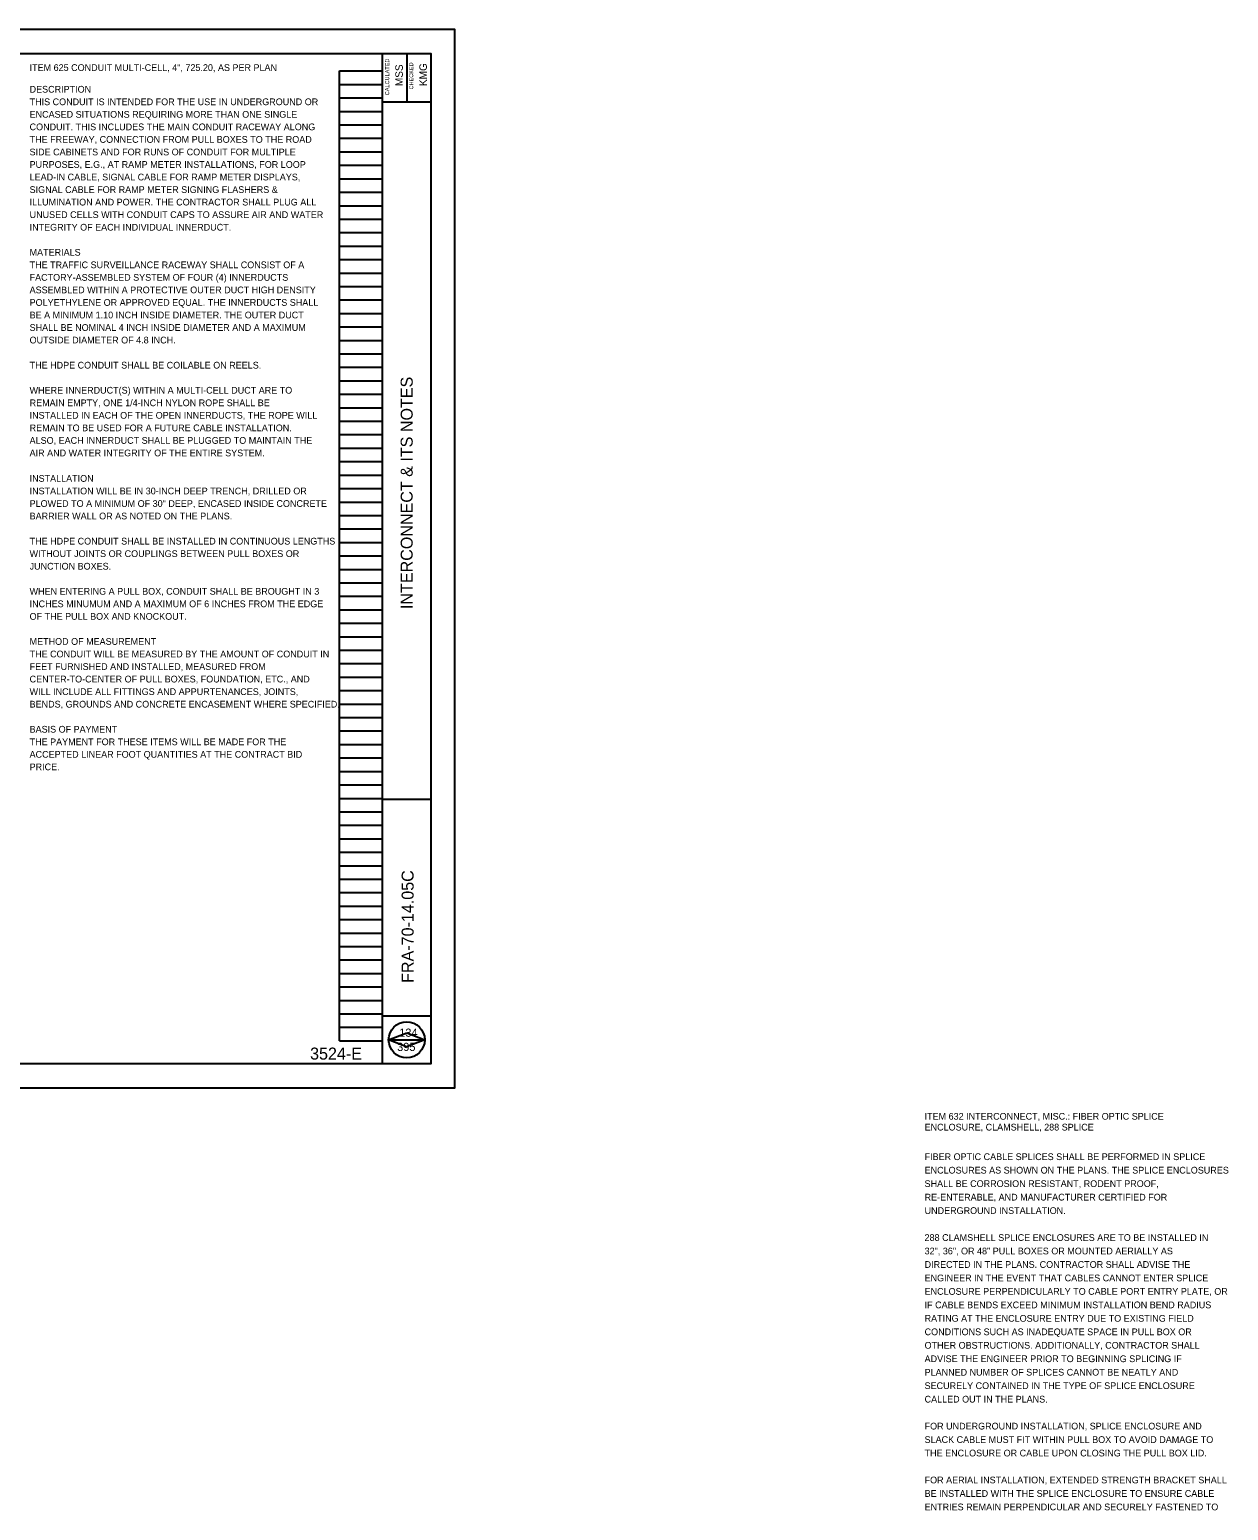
# Model space of a CAD drawing. Extents: x -36.9 to 49.6, y -47.1 to 37.
# Drawn here: x 24.65 to 49.58, y -16.29 to 14.49 of the extents above; entities that cross this region are included whole.
import ezdxf

# ---------------------------------------------------------------- set-up
doc = ezdxf.new("R2010")
doc.units = 0
for name, color, linetype in [('Level 63', 7, 'Continuous'), ('PF_P_Text', 7, 'Continuous'), ('SC_Scratch1', 7, 'Continuous'), ('SH_Cut_Line', 7, 'Continuous'), ('SH_Data', 7, 'Continuous'), ('SH_Text', 7, 'Continuous')]:
    doc.layers.add(name, color=color, linetype=linetype)

msp = doc.modelspace()

# ---------------------------------------------------------------- linework, layer by layer
at = {"layer": 'Level 63'}
msp.add_line((32.119, -6.508), (32.869, -6.508), dxfattribs=at)
msp.add_circle((32.494, -6.508), 0.375, dxfattribs=at)
at = {"layer": 'PF_P_Text'}
for p, q in [((31.994, -7.008), (31.994, 13.992)), ((32.494, 13.992), (32.494, 12.992)), ((31.994, 12.992), (32.994, 12.992)), ((31.994, -1.508), (32.994, -1.508)), ((31.994, -6.008), (32.994, -6.008))]:
    msp.add_line(p, q, dxfattribs=at)
msp.add_lwpolyline([(1.494, 13.992), (32.994, 13.992), (32.994, -7.008), (1.494, -7.008)], close=True, dxfattribs=at)
at = {"layer": 'SC_Scratch1'}
for p, q in [((31.094, -6.528), (31.094, 13.632)), ((31.094, 13.632), (31.994, 13.632)), ((31.994, -6.528), (31.994, 13.632)), ((31.094, 13.352), (31.994, 13.352)), ((31.094, 13.072), (31.994, 13.072)), ((31.094, 12.792), (31.994, 12.792)), ((31.094, 12.512), (31.994, 12.512)), ((31.094, 12.232), (31.994, 12.232)), ((31.094, 11.952), (31.994, 11.952)), ((31.094, 11.672), (31.994, 11.672)), ((31.094, 11.392), (31.994, 11.392)), ((31.094, 11.112), (31.994, 11.112)), ((31.094, 10.832), (31.994, 10.832)), ((31.094, 10.552), (31.994, 10.552)), ((31.094, 10.272), (31.994, 10.272)), ((31.094, 9.992), (31.994, 9.992)), ((31.094, 9.712), (31.994, 9.712)), ((31.094, 9.432), (31.994, 9.432)), ((31.094, 9.152), (31.994, 9.152)), ((31.094, 8.872), (31.994, 8.872)), ((31.094, 8.592), (31.994, 8.592)), ((31.094, 8.312), (31.994, 8.312)), ((31.094, 8.032), (31.994, 8.032)), ((31.094, 7.752), (31.994, 7.752)), ((31.094, 7.472), (31.994, 7.472)), ((31.094, 7.192), (31.994, 7.192)), ((31.094, 6.912), (31.994, 6.912)), ((31.094, 6.632), (31.994, 6.632)), ((31.094, 6.352), (31.994, 6.352)), ((31.094, 6.072), (31.994, 6.072)), ((31.094, 5.792), (31.994, 5.792)), ((31.094, 5.512), (31.994, 5.512)), ((31.094, 5.232), (31.994, 5.232)), ((31.094, 4.952), (31.994, 4.952)), ((31.094, 4.672), (31.994, 4.672)), ((31.094, 4.392), (31.994, 4.392)), ((31.094, 4.112), (31.994, 4.112)), ((31.094, 3.832), (31.994, 3.832)), ((31.094, 3.552), (31.994, 3.552)), ((31.094, 3.272), (31.994, 3.272)), ((31.094, 2.992), (31.994, 2.992)), ((31.094, 2.712), (31.994, 2.712)), ((31.094, 2.432), (31.994, 2.432)), ((31.094, 2.152), (31.994, 2.152)), ((31.094, 1.872), (31.994, 1.872)), ((31.094, 1.592), (31.994, 1.592)), ((31.094, 1.312), (31.994, 1.312)), ((31.094, 1.032), (31.994, 1.032)), ((31.094, 0.752), (31.994, 0.752)), ((31.094, 0.472), (31.994, 0.472)), ((31.094, 0.192), (31.994, 0.192)), ((31.094, -0.088), (31.994, -0.088)), ((31.094, -0.368), (31.994, -0.368)), ((31.094, -0.648), (31.994, -0.648)), ((31.094, -0.928), (31.994, -0.928)), ((31.094, -1.208), (31.994, -1.208)), ((31.094, -1.488), (31.994, -1.488)), ((31.094, -1.768), (31.994, -1.768)), ((31.094, -2.048), (31.994, -2.048)), ((31.094, -2.328), (31.994, -2.328)), ((31.094, -2.608), (31.994, -2.608)), ((31.094, -2.888), (31.994, -2.888)), ((31.094, -3.168), (31.994, -3.168)), ((31.094, -3.448), (31.994, -3.448)), ((31.094, -3.728), (31.994, -3.728)), ((31.094, -4.008), (31.994, -4.008)), ((31.094, -4.288), (31.994, -4.288)), ((31.094, -4.568), (31.994, -4.568)), ((31.094, -4.848), (31.994, -4.848)), ((31.094, -5.128), (31.994, -5.128)), ((31.094, -5.408), (31.994, -5.408)), ((31.094, -5.688), (31.994, -5.688)), ((31.094, -5.968), (31.994, -5.968)), ((31.094, -6.248), (31.994, -6.248)), ((32.119, -6.508), (32.495, -6.36)), ((32.495, -6.36), (32.869, -6.508)), ((31.094, -6.528), (31.994, -6.528)), ((32.49, -6.654), (32.119, -6.508)), ((32.869, -6.508), (32.49, -6.654))]:
    msp.add_line(p, q, dxfattribs=at)
at = {"layer": 'SH_Cut_Line'}
msp.add_lwpolyline([(-0.506, -7.508), (33.494, -7.508), (33.494, 14.492), (-0.506, 14.492)], close=True, dxfattribs=at)

# ---------------------------------------------------------------- texts
at = {"layer": 'Level 63'}
for s, p in [('CALCULATED', (32.13, 13.129)), ('CHECKED', (32.63, 13.248))]:
    msp.add_text(s, height=0.0833, rotation=90, dxfattribs=at).set_placement(p)
at = {"layer": 'SH_Data'}
for s, p in [('DESCRIPTION', (24.654, 13.182)), ('THIS CONDUIT IS INTENDED FOR THE USE IN UNDERGROUND OR ', (24.654, 12.921)), ('ENCASED SITUATIONS REQUIRING MORE THAN ONE SINGLE ', (24.654, 12.66)), ('CONDUIT. THIS INCLUDES THE MAIN CONDUIT RACEWAY ALONG ', (24.654, 12.4)), ('THE FREEWAY, CONNECTION FROM PULL BOXES TO THE ROAD ', (24.654, 12.139)), ('SIDE CABINETS AND FOR RUNS OF CONDUIT FOR MULTIPLE ', (24.654, 11.878)), ('PURPOSES, E.G., AT RAMP METER INSTALLATIONS, FOR LOOP ', (24.654, 11.618)), ('LEAD-IN CABLE, SIGNAL CABLE FOR RAMP METER DISPLAYS, ', (24.654, 11.357)), ('SIGNAL CABLE FOR RAMP METER SIGNING FLASHERS & ', (24.654, 11.096)), ('ILLUMINATION AND POWER. THE CONTRACTOR SHALL PLUG ALL ', (24.654, 10.836)), ('UNUSED CELLS WITH CONDUIT CAPS TO ASSURE AIR AND WATER ', (24.654, 10.575)), ('INTEGRITY OF EACH INDIVIDUAL INNERDUCT.', (24.654, 10.314)), ('MATERIALS', (24.654, 9.793)), ('THE TRAFFIC SURVEILLANCE RACEWAY SHALL CONSIST OF A ', (24.654, 9.532)), ('FACTORY-ASSEMBLED SYSTEM OF FOUR (4) INNERDUCTS ', (24.654, 9.271)), ('ASSEMBLED WITHIN A PROTECTIVE OUTER DUCT HIGH DENSITY ', (24.654, 9.011)), ('POLYETHYLENE OR APPROVED EQUAL. THE INNERDUCTS SHALL ', (24.654, 8.75)), ('BE A MINIMUM 1.10 INCH INSIDE DIAMETER. THE OUTER DUCT ', (24.654, 8.489)), ('SHALL BE NOMINAL 4 INCH INSIDE DIAMETER AND A MAXIMUM ', (24.654, 8.229)), ('OUTSIDE DIAMETER OF 4.8 INCH.', (24.654, 7.968)), ('THE HDPE CONDUIT SHALL BE COILABLE ON REELS. ', (24.654, 7.446)), ('WHERE INNERDUCT(S) WITHIN A MULTI-CELL DUCT ARE TO ', (24.654, 6.925)), ('REMAIN EMPTY, ONE 1/4-INCH NYLON ROPE SHALL BE ', (24.654, 6.664)), ('INSTALLED IN EACH OF THE OPEN INNERDUCTS, THE ROPE WILL ', (24.654, 6.404)), ('REMAIN TO BE USED FOR A FUTURE CABLE INSTALLATION. ', (24.654, 6.143)), ('ALSO, EACH INNERDUCT SHALL BE PLUGGED TO MAINTAIN THE ', (24.654, 5.882)), ('AIR AND WATER INTEGRITY OF THE ENTIRE SYSTEM.', (24.654, 5.622)), ('ENCLOSURE, CLAMSHELL, 288 SPLICE', (43.262, -8.393)), ('ITEM 632 INTERCONNECT, MISC.: FIBER OPTIC SPLICE ', (43.262, -8.168))]:
    msp.add_text(s, height=0.14, dxfattribs=at).set_placement(p)
at = {"layer": 'SH_Text'}
for s, height, rotation, p in [('ITEM 625 CONDUIT MULTI-CELL, 4", 725.20, AS PER PLAN', 0.14, 0.005, (24.654, 13.632)), ('MSS', 0.156, 90, (32.414, 13.317)), ('KMG', 0.156, 90, (32.914, 13.319)), ('INTERCONNECT & ITS NOTES', 0.25, 90, (32.619, 2.447)), ('FRA-70-14.05C', 0.25, 90, (32.639, -5.324)), ('3524-E', 0.25, 359.9999, (30.486, -6.919))]:
    msp.add_text(s, height=height, rotation=rotation, dxfattribs=at).set_placement(p)
for s, height, p in [('INSTALLATION ', 0.14, (24.654, 5.092)), ('INSTALLATION WILL BE IN 30-INCH DEEP TRENCH, DRILLED OR ', 0.14, (24.654, 4.831)), ('PLOWED TO A MINIMUM OF 30" DEEP, ENCASED INSIDE CONCRETE ', 0.14, (24.654, 4.57)), ('BARRIER WALL OR AS NOTED ON THE PLANS. ', 0.14, (24.654, 4.31)), ('THE HDPE CONDUIT SHALL BE INSTALLED IN CONTINUOUS LENGTHS ', 0.14, (24.654, 3.788)), ('WITHOUT JOINTS OR COUPLINGS BETWEEN PULL BOXES OR ', 0.14, (24.654, 3.528)), ('JUNCTION BOXES. ', 0.14, (24.654, 3.267)), ('WHEN ENTERING A PULL BOX, CONDUIT SHALL BE BROUGHT IN 3 ', 0.14, (24.654, 2.745)), ('INCHES MINUMUM AND A MAXIMUM OF 6 INCHES FROM THE EDGE ', 0.14, (24.654, 2.485)), ('OF THE PULL BOX AND KNOCKOUT. ', 0.14, (24.654, 2.224)), ('THE CONDUIT WILL BE MEASURED BY THE AMOUNT OF CONDUIT IN ', 0.14, (24.654, 1.442)), ('METHOD OF MEASUREMENT', 0.14, (24.654, 1.703)), ('FEET FURNISHED AND INSTALLED, MEASURED FROM ', 0.14, (24.654, 1.181)), ('CENTER-TO-CENTER OF PULL BOXES, FOUNDATION, ETC., AND ', 0.14, (24.654, 0.921)), ('WILL INCLUDE ALL FITTINGS AND APPURTENANCES, JOINTS, ', 0.14, (24.654, 0.66)), ('BENDS, GROUNDS AND CONCRETE ENCASEMENT WHERE SPECIFIED. ', 0.14, (24.654, 0.399)), ('BASIS OF PAYMENT', 0.14, (24.654, -0.122)), ('THE PAYMENT FOR THESE ITEMS WILL BE MADE FOR THE ', 0.14, (24.654, -0.383)), ('ACCEPTED LINEAR FOOT QUANTITIES AT THE CONTRACT BID ', 0.14, (24.654, -0.644)), ('PRICE.', 0.14, (24.654, -0.904)), ('134', 0.17, (32.34, -6.444)), ('395', 0.17, (32.297, -6.74)), ('FIBER OPTIC CABLE SPLICES SHALL BE PERFORMED IN SPLICE ', 0.14, (43.262, -9.008)), ('ENCLOSURES AS SHOWN ON THE PLANS. THE SPLICE ENCLOSURES ', 0.14, (43.262, -9.288)), ('SHALL BE CORROSION RESISTANT, RODENT PROOF, ', 0.14, (43.262, -9.568)), ('RE-ENTERABLE, AND MANUFACTURER CERTIFIED FOR ', 0.14, (43.262, -9.848)), ('UNDERGROUND INSTALLATION.', 0.14, (43.262, -10.128)), ('288 CLAMSHELL SPLICE ENCLOSURES ARE TO BE INSTALLED IN ', 0.14, (43.262, -10.688)), ('32", 36", OR 48" PULL BOXES OR MOUNTED AERIALLY AS ', 0.14, (43.262, -10.968)), ('DIRECTED IN THE PLANS. CONTRACTOR SHALL ADVISE THE ', 0.14, (43.262, -11.248)), ('ENGINEER IN THE EVENT THAT CABLES CANNOT ENTER SPLICE ', 0.14, (43.262, -11.528)), ('ENCLOSURE PERPENDICULARLY TO CABLE PORT ENTRY PLATE, OR ', 0.14, (43.262, -11.808)), ('IF CABLE BENDS EXCEED MINIMUM INSTALLATION BEND RADIUS ', 0.14, (43.262, -12.088)), ('RATING AT THE ENCLOSURE ENTRY DUE TO EXISTING FIELD ', 0.14, (43.262, -12.368)), ('CONDITIONS SUCH AS INADEQUATE SPACE IN PULL BOX OR ', 0.14, (43.262, -12.648)), ('OTHER OBSTRUCTIONS. ADDITIONALLY, CONTRACTOR SHALL ', 0.14, (43.262, -12.928)), ('ADVISE THE ENGINEER PRIOR TO BEGINNING SPLICING IF ', 0.14, (43.262, -13.208)), ('PLANNED NUMBER OF SPLICES CANNOT BE NEATLY AND ', 0.14, (43.262, -13.488)), ('SECURELY CONTAINED IN THE TYPE OF SPLICE ENCLOSURE ', 0.14, (43.262, -13.768)), ('CALLED OUT IN THE PLANS.', 0.14, (43.262, -14.048)), ('FOR UNDERGROUND INSTALLATION, SPLICE ENCLOSURE AND ', 0.14, (43.262, -14.608)), ('SLACK CABLE MUST FIT WITHIN PULL BOX TO AVOID DAMAGE TO ', 0.14, (43.262, -14.888)), ('THE ENCLOSURE OR CABLE UPON CLOSING THE PULL BOX LID.', 0.14, (43.262, -15.168)), ('FOR AERIAL INSTALLATION, EXTENDED STRENGTH BRACKET SHALL ', 0.14, (43.262, -15.728)), ('BE INSTALLED WITH THE SPLICE ENCLOSURE TO ENSURE CABLE ', 0.14, (43.262, -16.008)), ('ENTRIES REMAIN PERPENDICULAR AND SECURELY FASTENED TO ', 0.14, (43.262, -16.288))]:
    msp.add_text(s, height=height, dxfattribs=at).set_placement(p)

doc.saveas('drawing.dxf')
